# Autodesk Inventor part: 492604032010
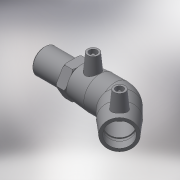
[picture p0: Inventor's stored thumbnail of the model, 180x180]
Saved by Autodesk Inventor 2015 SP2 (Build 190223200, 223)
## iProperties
Created: 2017-06
Part Number: 492604032010
Material: Generic
Description: PLASSON 45° ELBOW TRANSITION MALE 32-1"
Document SubType Name: Modeling
Designer: KIM
Mass: 113.664 g
Surface Area: 338.322 cm^2
Volume: 113.664 cm^3
Density: 1 g/cm^3
Appearance: Default
Author: KIM
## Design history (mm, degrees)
derived "492604.ipt"
feature "Solid1::492604.ipt"
tag "TaggingFeature1"
body "Solid1"
other parameters: "d2" = 44, "d4" = 23.75, "d5" = 39.6, "d8" = 168 deg, "d10" = 15.6, "d11" = 5.2, "d29" = 43, "d30" = 15, "d31" = 33.25, "d34" = 5 deg, "d41" = 4, "d42" = 14, "d43" = 0, "d49" = 32, "d50" = 20.8, "d51" = 15.6, "d52" = 40.17, "d54" = 135 deg, "d86" = 19.8, "d87" = 135 deg, "d88" = 95, "d90" = 39, "d91" = 0, "d92" = 39, "d93" = 0, "d101" = 3, "d102" = 0, "d107" = 0.1, "d108" = 23, "d109" = 33.249, "d110" = 34, "d111" = 8.5, "d112" = 44, "d113" = 23.2743, "d114" = 30.6, "d116" = 1.32, "d122" = 0, "d123" = 1.66245, "d_" = 32, "L_" = 129, "L_1" = 39, "D_" = 23, "A_" = 43, "d_2" = 12, "L_2" = 34, "R_" = 33.249, "D_1" = 44
